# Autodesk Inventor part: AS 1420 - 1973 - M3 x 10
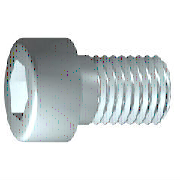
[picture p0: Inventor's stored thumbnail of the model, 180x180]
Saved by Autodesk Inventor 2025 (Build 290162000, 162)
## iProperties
Created: 2024-01
Part Number: AS 1420 - 1973 - M3 x 10
Material: Acciaio, Dolce
Description: Viti con esagono incassato metriche ISO
Document SubType Name: Modeling
Standard: AS 1420 - 1973
Designer: R5800u
Standards Organization: AS
Language: it-IT
Size Designation: M3 x 10
Categories: <MemberInstance><Categories><Category DisplayName="Elementi di fissaggio" InternalName="e4da775c-781d-43d5-af7c-5136215cf5a6" Mnemonic="FSTN"><Category DisplayN
Density: 7.85 g/cm^3
Appearance: Semilucidato
IsCustomPart: 0
Author: R5800u
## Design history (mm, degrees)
body "Solid1"
workplane "Work Plane1"
fillet "Fillet2" dims "d30" = 0.1 (= R)
revolve "Corpo" stored, may be unused: angle "d10" = 90 deg
sketch "Schizzo2"
  geometry: L1 (0, -3.85)-(0, 3.85) reference; L2 (-3.85, 0)-(3.85, 0) reference; L3 (1.443, 0)-(0.722, -1.25); L4 (0.722, -1.25)-(-0.722, -1.25); L5 (-0.722, -1.25)-(-1.443, 0); L6 (-1.443, 0)-(-0.722, 1.25); L7 (-0.722, 1.25)-(0.722, 1.25); L8 (0.722, 1.25)-(1.443, 0); 2 further points
  constraints: 12 end point, 1 coincident, 1 horizontal alignment, 1 point on line, 12 other
extrude "Intaglio" join sketch "Schizzo2" stored distance "d11" = 10; taper "d12" = 0 deg
fillet "Raccordo1" dims "d17" = 0.3 (= RR)
feature "Filettatura" dims "d13" = 8.75 (= GEL), "d14" = 0
chamfer "Smusso1" distance "d15" = 0.30673 (= -0.5 x SPD + 0.5 x GD); stored, may be unused: second distance "d16" = 0.30673 (= GUL), angle "d27" = 45 deg
sketch "Schizzo1"
  geometry: L1 (-0.867, 0)-(10, 0); L2 (10, 0)-(10, 1.5); L3 (10, 1.5)-(1.25, 1.5); L4 (1.25, 1.5)-(0.943, 1.5); L5 (0.943, 1.5)-(0, 1.5); L6 (0, 1.5)-(0, 2.75); L7 (0, 2.75)-(-3, 2.75); L8 (-3, 2.75)-(-3, 1.443); L9 (-3, 1.443)-(-1.7, 1.443); L10 (-1.7, 1.443)-(-0.867, 0); L11 (-5.6, 0)-(12.6, 0) reference; L12 (0, -0.55)-(0, 3.3) reference; L13 (1.25, 1.5)-(0, 1.5)
  constraints: 22 end point, 6 parallel, 2 collinear, 2 perpendicular, 1 horizontal, 1 point on line
  dimensions: "d1" = 8.75 distance from line of L3.end L2 (= GEL); "d2" = 0.30683 distance of L4.end L3.end (computed from GAL); "d3" = 3 distance between parallel lines of L8 L6 (= KOH); "d4" = 1.3 distance of L8.end L9.end (= INTI); "d5" = 60 deg angle of L10 L1; "d6" = 3 diameter of L3 L1 (= GD); "d7" = 3 diameter of L5 L1 (= BDM); "d8" = 2.88675 diameter of L9 L1 (= 1.1547 x SW); "d9" = 5.5 diameter of L7 L1 (= KOD); "d26" = 10 distance between parallel lines of L12 L2 (= NLG)
other parameters: "GD" = 3 (= NND) [user parameter; used in 2 equation terms], "NLG" = 10 [user parameter; used in 1 equation term], "GEL" = 8.75 [user parameter; used in 2 equation terms], "KOD" = 5.5 [user parameter; used in 1 equation term], "KOH" = 3 (= NND) [user parameter; used in 1 equation term], "INTI" = 1.3 [user parameter; used in 1 equation term], "GAL" = 0.30673 (= 0.61345 x PTC) [user parameter; used in 1 equation term], "GUL" = 0.30673 (= 0.61345 x PTC) [user parameter; used in 1 equation term], "BDM" = 3 (= NND) [user parameter; used in 1 equation term], "SW" = 2.5 [user parameter; used in 2 equation terms], "RR" = 0.3 (= 0.1 x NND) [user parameter; used in 1 equation term], "SPD" = 2.38655 (= NND - 1.2269 x PTC) [user parameter; used in 1 equation term], "d19" = 0, "d28" = 0, "d29" = 0, "R" = 0.1 [user parameter; used in 1 equation term], "PHH" = 0.13 [user parameter], "GD1" = 2.38655 (= THREADDIA - 1.2269 x PTC) [user parameter], "THREADDIA" = 3 [user parameter; used in 1 equation term], "FAWI" = 45 deg [user parameter], "PTC" = 0.5 [user parameter; used in 5 equation terms], "KOH1" = 2.7 [user parameter], "NND" = 3 [user parameter; used in 5 equation terms], "TOA" = 30 deg [user parameter], "E0" = 2.8875 (= 1.155 x SW) [user parameter]
